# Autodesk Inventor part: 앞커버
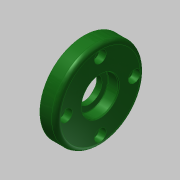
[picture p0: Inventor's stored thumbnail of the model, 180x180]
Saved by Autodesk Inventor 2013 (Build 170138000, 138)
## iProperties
Created: 2015-11
Part Number: 앞커버
Material: 알루미늄 6061
Document SubType Name: Modeling
Designer: mduedu
Density: 1 g/cm^3
Author: mduedu
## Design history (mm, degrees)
sketch "스케치5"
  geometry: C1 r 30 at (0, 0); 2 further points
  constraints: 2 coincident, 1 centre point
  dimensions: "d66" = 60 diameter of C1
extrude "돌출2" new body sketch "스케치5" distance "d67" = 11; taper "d68" = 0 deg
sketch "스케치6"
  geometry: C1 r 16 at (0, 0); 1 further point
  constraints: 1 centre point, 1 coincident
  dimensions: "d69" = 32 diameter of C1
extrude "돌출3" join sketch "스케치6" distance "d70" = 3; taper "d71" = 0 deg
hole "구멍7" diameter "d98" = 25; stored, may be unused: countersink angle "d102" = 90 deg, drill point angle "d104" = 0 deg; dims "d96" = 10, "d97" = 10, "d99" = 6, "d100" = 4, "d101" = 2, "d103" = 3
hole "구멍8" diameter "d107" = 25; stored, may be unused: countersink angle "d111" = 90 deg, drill point angle "d113" = 0 deg; dims "d108" = 6, "d109" = 4, "d110" = 2, "d112" = 7.3, "d143" = 10, "d144" = 10
hole "구멍9" diameter "d116" = 17; stored, may be unused: countersink angle "d120" = 90 deg, drill point angle "d122" = 0 deg; dims "d114" = 10, "d115" = 10, "d117" = 6, "d118" = 4, "d119" = 2, "d121" = 7.7
chamfer "모따기2" distance "d123" = 0.7; stored, may be unused: second distance "d124" = 2, angle "d125" = 30 deg
fillet "모깎기11" dims "d126" = 0.3
fillet "모깎기13" dims "d128" = 3
fillet "모깎기14" dims "d129" = 3
fillet "모깎기15" dims "d130" = 0.3
sketch "스케치8" dims "d131" = 46
  geometry: 3 further points
  constraints: 2 vertical alignment, 1 coincident, 2 other
hole "구멍10" sketch "스케치8" at (0, 23) diameter "d132" = 4.5; stored, may be unused: countersink angle "d136" = 90 deg, drill point angle "d138" = 0 deg; dims "d133" = 6, "d134" = 8, "d135" = 4.6, "d137" = 7.7
node "솔리드2"
pattern_circular "원형 패턴4" dims angle "d140" = 360 deg
